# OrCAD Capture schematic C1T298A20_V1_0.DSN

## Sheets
1 000_Log: title: TELINK; rev: V1.3; note: C1T298A20
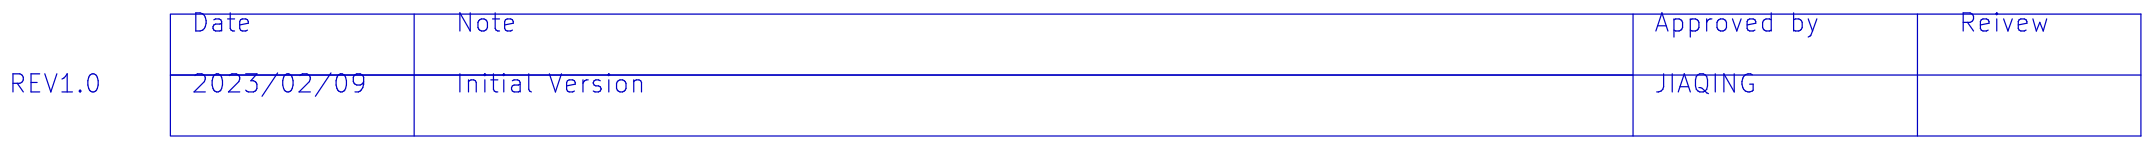
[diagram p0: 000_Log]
2 001_Structure
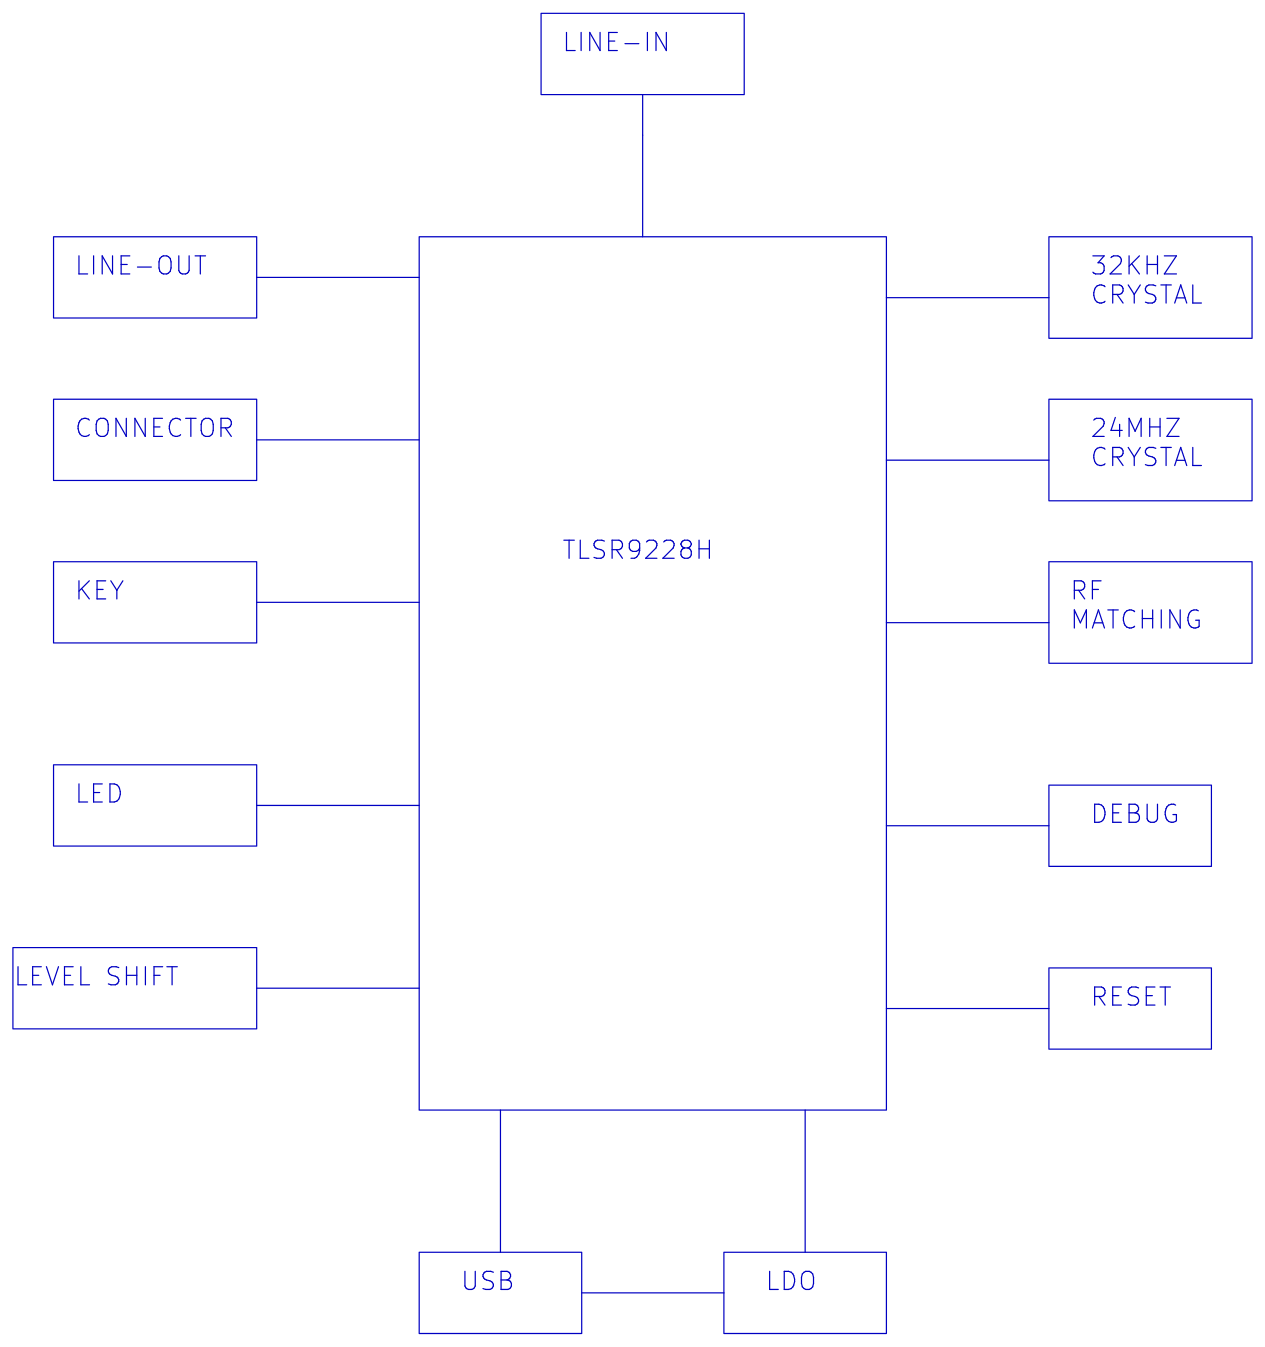
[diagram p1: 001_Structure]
3 002_MCU: size A3
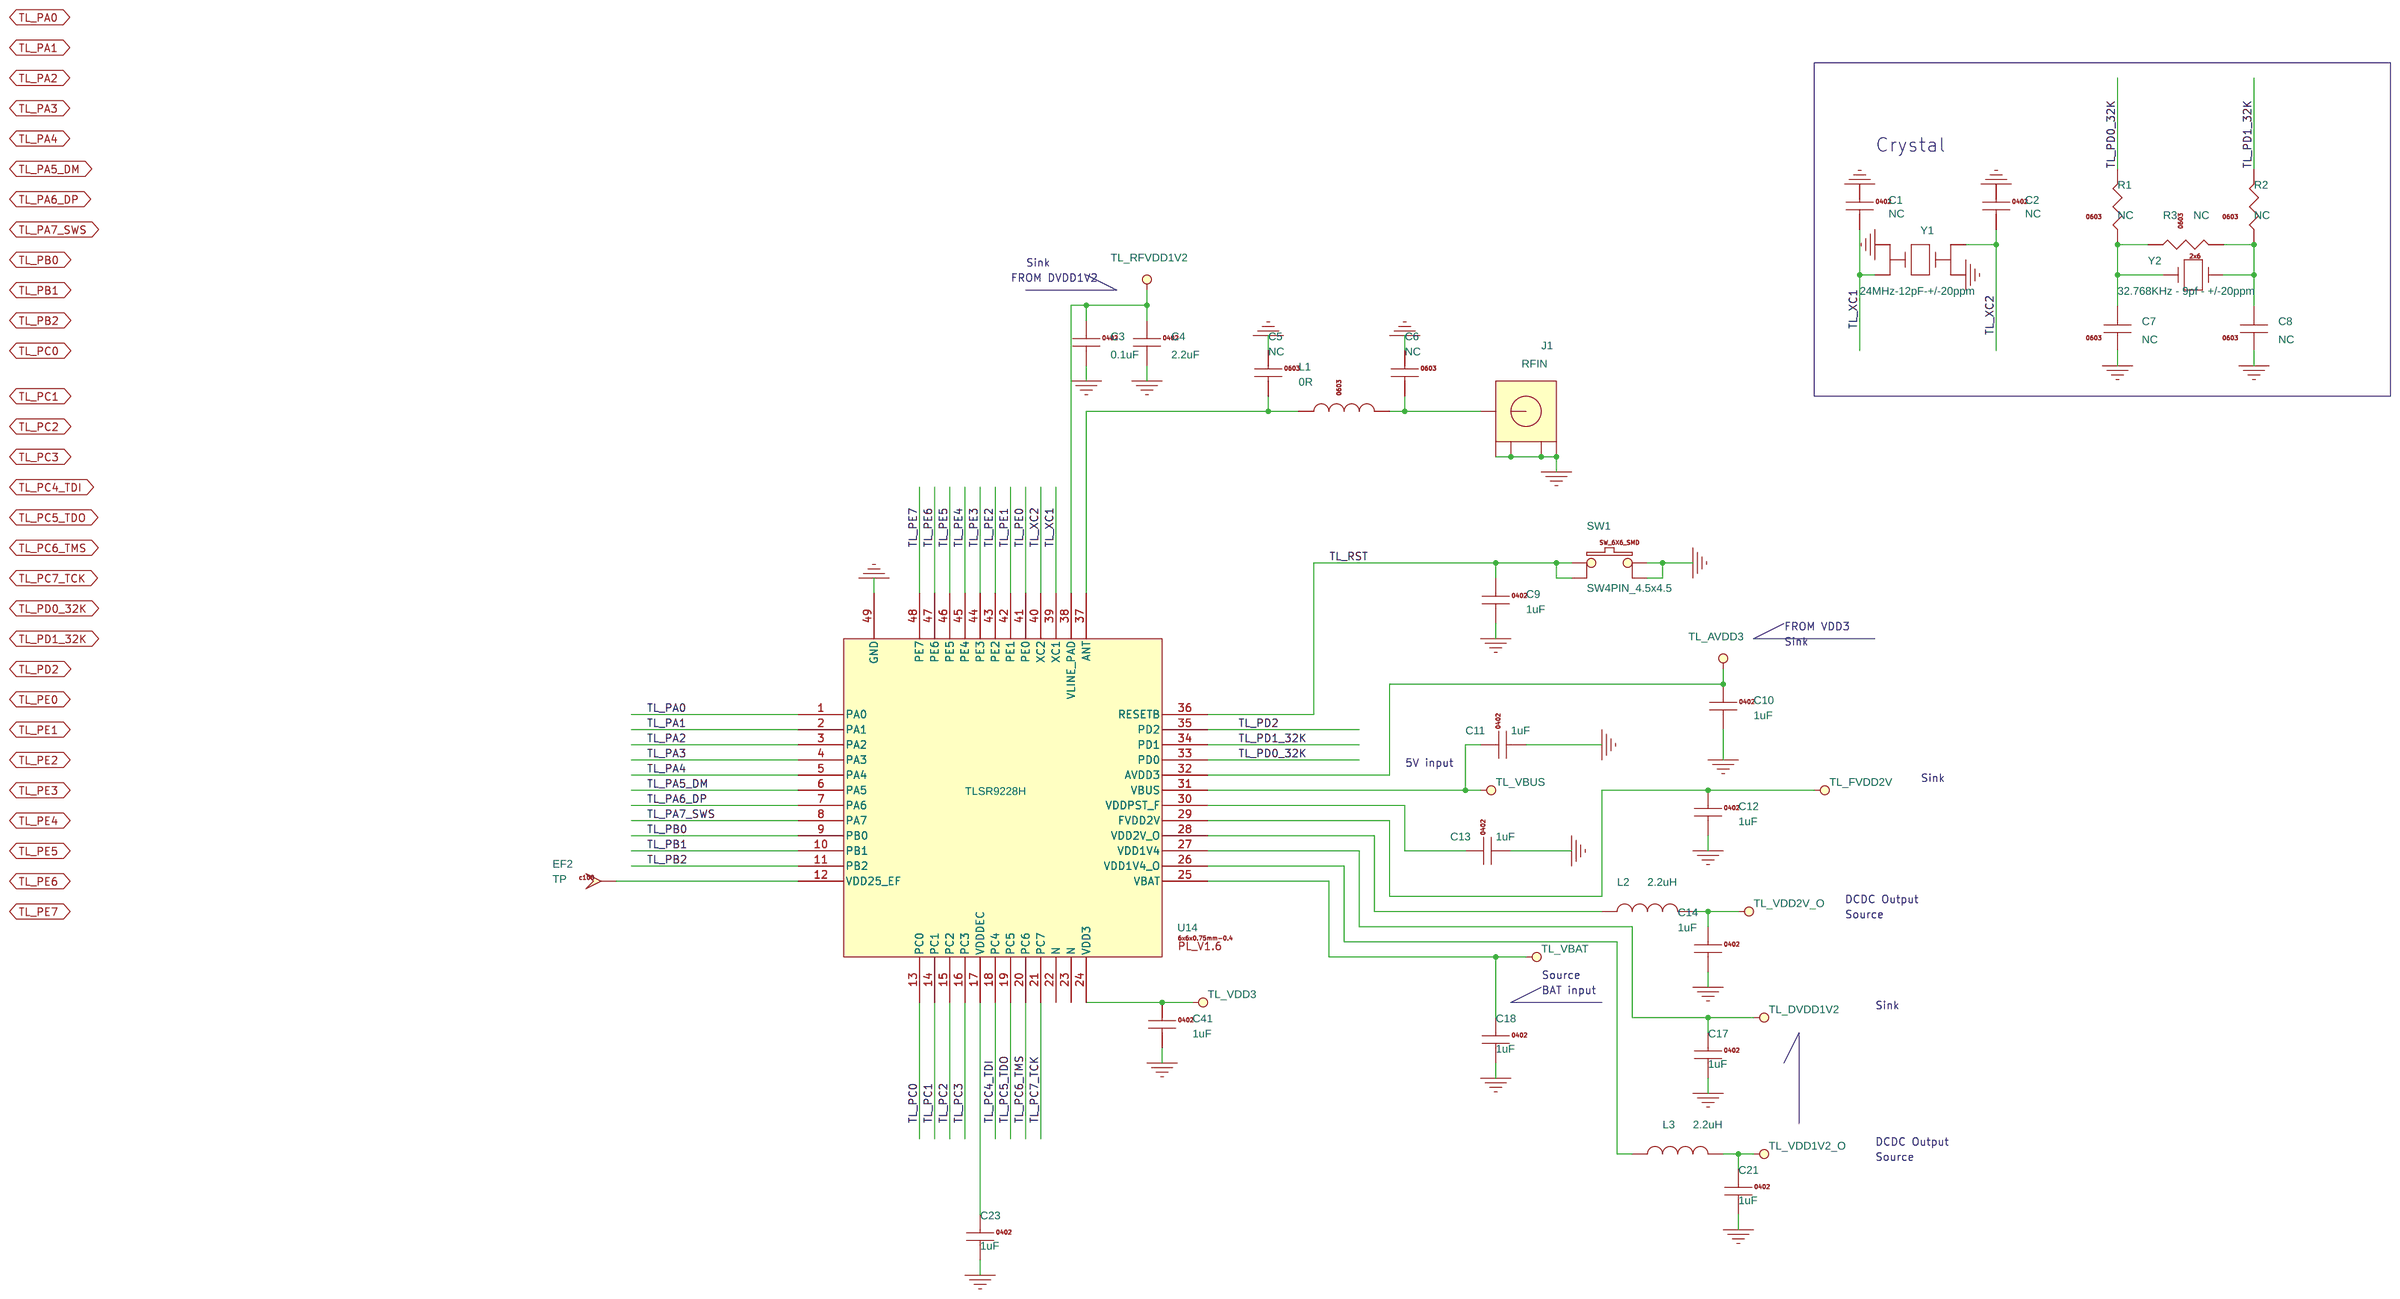
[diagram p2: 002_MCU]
4 003_INTERFACE: size A3
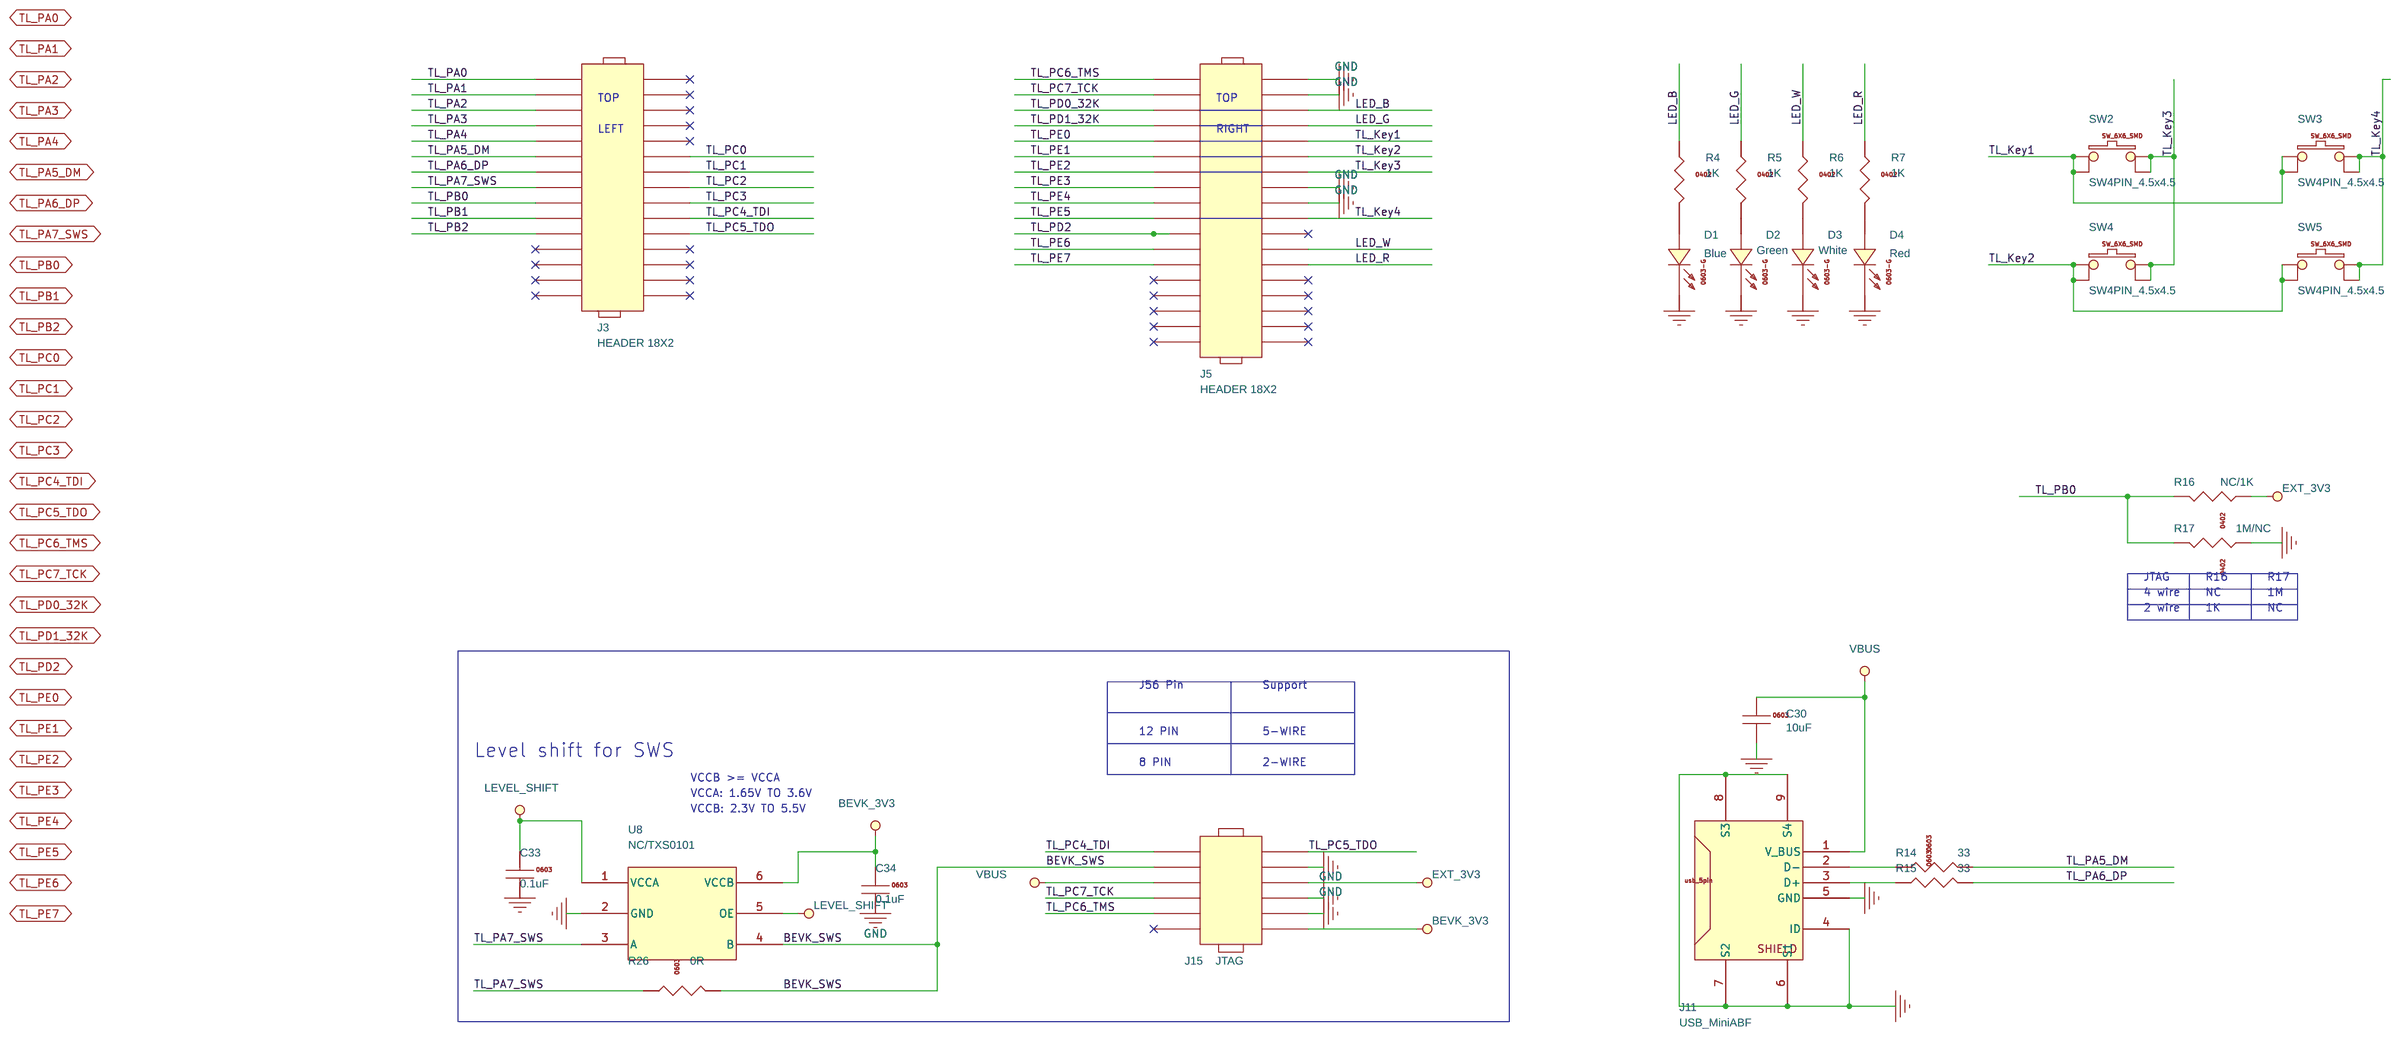
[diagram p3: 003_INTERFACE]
5 004_POWER: size A3
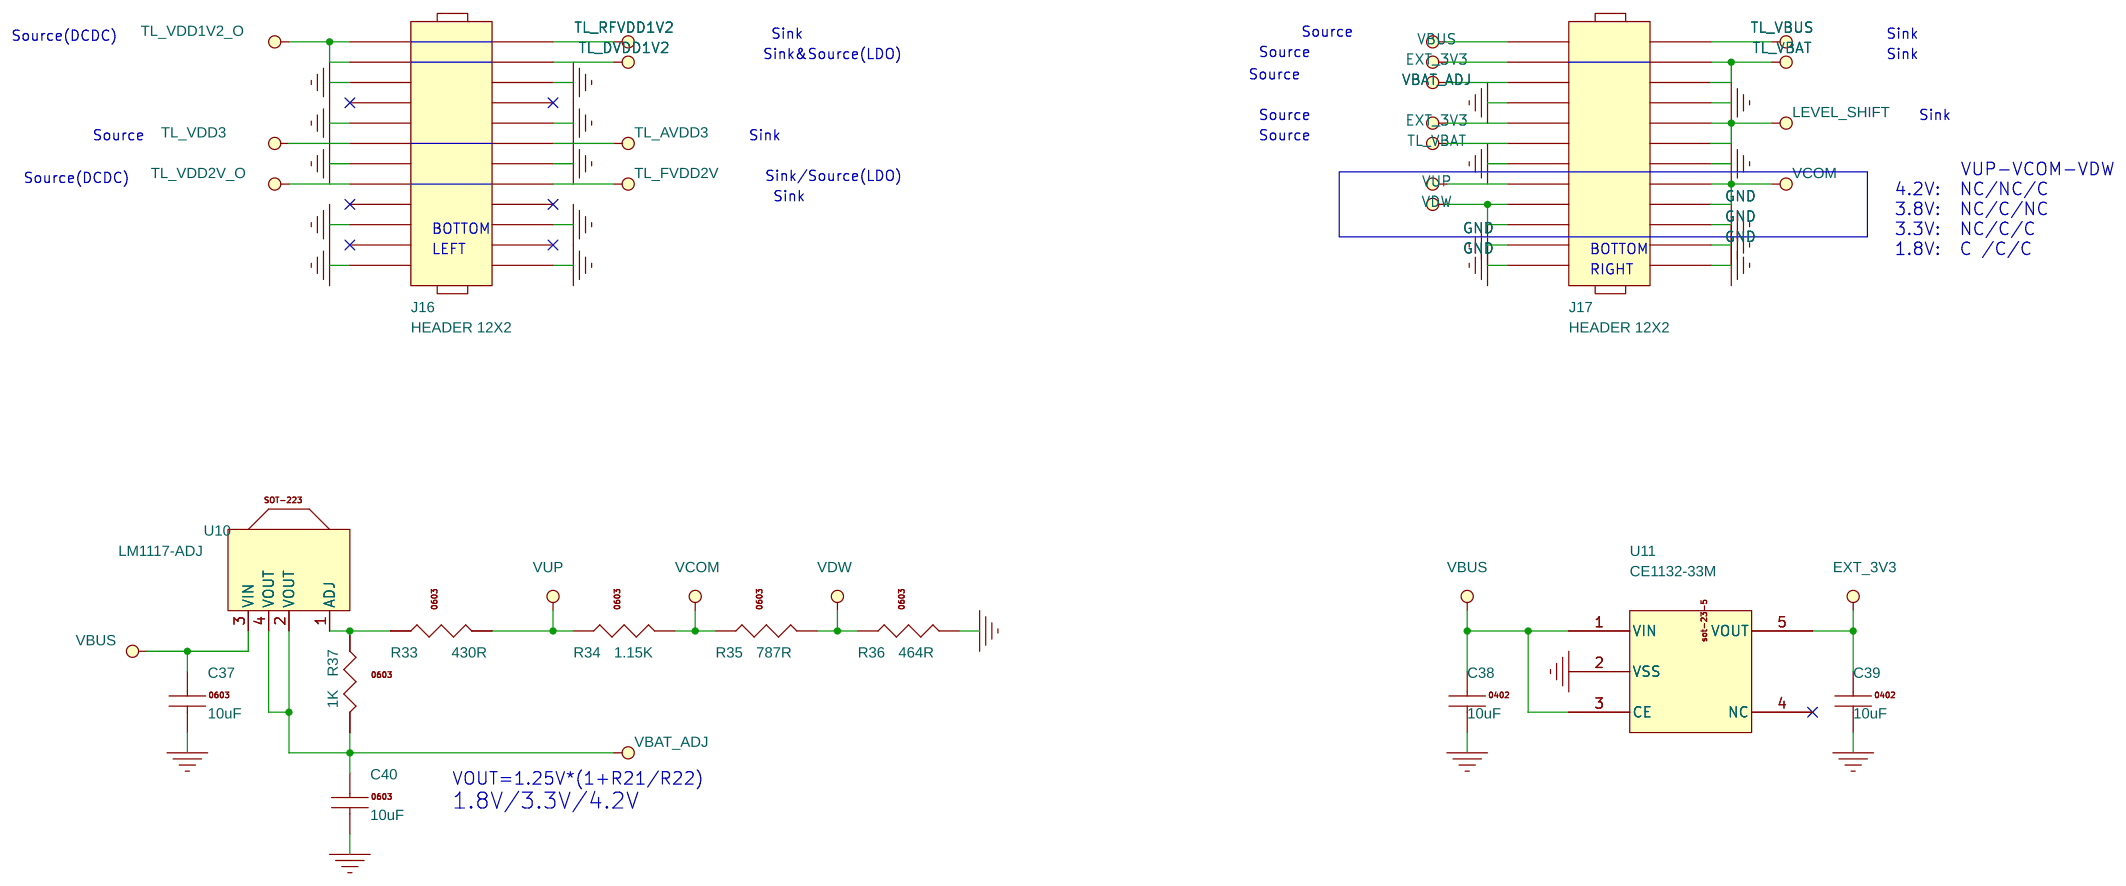
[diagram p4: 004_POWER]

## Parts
sheet 002_MCU
C1  NC  [0402]
C2  NC  [0402]
C3  0.1uF  [0402]
C4  2.2uF  [0402]
C5  NC  [0402]
C6  NC  [0402]
C7  NC  [0402]
C8  NC  [0402]
C9  1uF  [0402]
C10  1uF  [0402]
C11  1uF  [0402]
C12  1uF  [0402]
C13  1uF  [0402]
C14  1uF  [0402]
C17  1uF  [0402]
C18  1uF  [0402]
C21  1uF  [0402]
C23  1uF  [0402]
C41  1uF  [0402]
EF2  TP  [TP100]
J1  RFIN  [SMA-H]
L1  0R  [0402]
L2  2.2uH  [0805L]
L3  2.2uH  [0805L]
R1  NC  [0402]
R2  NC  [0402]
R3  NC  [0402]
SW1  SW4PIN_4.5x4.5  [SW_6X6_SMD]
U14  TLSR9228H  [qfn_6x6_48pin_0p4_4p2x4p2]
Y1  24MHz-12pF-+/-20ppm  [OSCCC250X320X110]
Y2  32.768KHz - 9pf - +/-20ppm  [OSC_2x6]
sheet 003_INTERFACE
C30  10uF  [0603C]
C33  0.1uF  [0402]
C34  0.1uF  [0402]
D1  Blue  [0603-LED]
D2  Green  [0603-LED]
D3  White  [0603-LED]
D4  Red  [0603-LED]
J3  HEADER 18X2  [smd254m-2x15_rx1_30y2_40]
J5  HEADER 18X2  [smd254m-2x18_rx1_30y2_40]
J11  USB_MiniABF  [USB-MINI-F5]
J15  JTAG  [hdr254f-2x6x850]
R4  1K  [0402]
R5  1K  [0402]
R6  1K  [0402]
R7  1K  [0402]
R14  33  [0402R]
R15  33  [0402R]
R16  NC/1K  [0402]
R17  1M/NC  [0402]
R26  0R  [0402R]
SW2  SW4PIN_4.5x4.5  [SW_6X6_SMD]
SW3  SW4PIN_4.5x4.5  [SW_6X6_SMD]
SW4  SW4PIN_4.5x4.5  [SW_6X6_SMD]
SW5  SW4PIN_4.5x4.5  [SW_6X6_SMD]
U8  NC/TXS0101  [sc70-6]
sheet 004_POWER
C37  10uF  [0603c]
C38  10uF  [0603C]
C39  10uF  [0603C]
C40  10uF  [0603C]
J16  HEADER 12X2  [smd254m-2x12_rx1_30y2_40]
J17  HEADER 12X2  [smd254m-2x12_rx1_30y2_40]
R33  430R  [0402]
R34  1.15K  [0402]
R35  787R  [0402]
R36  464R  [0402]
R37  1K  [0402]
U10  LM1117-ADJ  [sot-223]
U11  CE1132-33M  [sot-23-5]

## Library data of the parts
C1 C2 = C1005_NC
C3 C4 C9-C14 C17 C18 C21 C23 C38 C39 C41 = C1005X5R1C104K
C5-C8 = C1608_NC
EF2 = TestPad100
J1 = SMA_JACK_2: PART: RF
L1 = MLK1608_000R
L2 L3 = IND
R1-R3 R26 = RS0603K102JT
SW1-SW5 = SW_6X6_SMD_0
U14 = TLSR9228H_0
Y1 = CRYSTAL4_SM_0
Y2 = OSC_2x6_2pin_16Mhz
C30 C37 = C1608X5R0J106M
C33 C34 C40 = C1608X5R1C105M
D1-D4 = 0603D_Green
J3 = HEADER_18X2_0
J5 = HEADER_18X2
J11 = USB_MiniABF_5pin
J15 = HEADER_6X2
R4-R7 = RS0402K102JT
R14 R15 = RS0603K330JT
R16 R17 = RS0402K104JT
U8 = TXS0101
J16 J17 = HEADER_12X2
R33-R37 = RS0603K104JT
U10 = XC62FP3302_0.3V_SOT-89
U11 = XC6219_6.3V_SOT-23-5

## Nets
GND: C1.1 C2.1 C3.2 C4.2 C5.1 C6.1 C7.1 C8.1 C9.2 C10.2 C11.2 C12.2 C13.2 C14.2 C17.2 C18.2 C21.2 C23.2 C30.2 C33.2 C34.2 C37.2 C38.2 C39.2 C40.2 C41.2 D1.C(CATHODE) D2.C(CATHODE) D3.C(CATHODE) D4.C(CATHODE) J1.2 J1.3 J1.4 J1.5 J5.1 J5.3 J5.15 J5.17 J11.4(ID) J11.5(GND) J11.6(S1) J11.7(S2) J11.8(S3) J11.9(S4) J15.3 J15.5 J15.9 J16.5 J16.6 J16.9 J16.10 J16.13 J16.14 J16.19 J16.20 J16.23 J16.24 J17.7 J17.8 J17.13 J17.14 J17.19 J17.21 J17.22 J17.23 J17.24 R17.1 R36.2 SW1.3 SW1.4 U8.2(GND) U11.2(VSS) U14.49(GND) Y1.2 Y1.4
VBAT_ADJ: C40.1 J17.6 R37.2 U10.2(VOUT) U10.4(VOUT)
VBUS: C30.1 C37.1 C38.1 J11.1(V_BUS) J15.8 J17.2 U10.3(VIN) U11.1(VIN) U11.3(CE)
BEVK_3V3: C34.1 J15.1 U8.6(VCCB)
BEVK_SWS: J15.10 R26.2 U8.4(B)
EXT_3V3: C39.1 J15.7 J17.4 J17.10 R16.1 U11.5(VOUT)
LED_B: J5.5 R4.1
LED_G: J5.7 R5.1
LED_R: J5.25 R7.1
LED_W: J5.23 R6.1
LEVEL_SHIFT: C33.1 J17.9 J17.11 U8.1(VCCA) U8.5(OE)
N: U14.22(N) U14.23(N)
TL_AVDD3: C10.1 J16.11 U14.32(AVDD3)
TL_DVDD1V2: C17.1 J16.3 U14.27(VDD1V4)
TL_FVDD2V: C12.1 J16.15 U14.29(FVDD2V)
TL_Key1: J5.9 SW2.1 SW2.2 SW3.1 SW3.2
TL_Key2: J5.11 SW4.1 SW4.2 SW5.1 SW5.2
TL_Key3: J5.13 SW2.3 SW2.4 SW4.3 SW4.4
TL_Key4: J5.19 SW3.3 SW3.4 SW5.3 SW5.4
TL_PA0: U14.1(PA0)
TL_PA0 (page 003_INTERFACE): J3.2
TL_PA1: U14.2(PA1)
TL_PA1 (page 003_INTERFACE): J3.4
TL_PA2: U14.3(PA2)
TL_PA2 (page 003_INTERFACE): J3.6
TL_PA3: U14.4(PA3)
TL_PA3 (page 003_INTERFACE): J3.8
TL_PA4: U14.5(PA4)
TL_PA4 (page 003_INTERFACE): J3.10
TL_PA5_DM: U14.6(PA5)
TL_PA5_DM (page 003_INTERFACE): J3.12 R14.2
TL_PA6_DP: U14.7(PA6)
TL_PA6_DP (page 003_INTERFACE): J3.14 R15.2
TL_PA7_SWS: U14.8(PA7)
TL_PA7_SWS (page 003_INTERFACE): J3.16 R26.1 U8.3(A)
TL_PB0: U14.9(PB0)
TL_PB0 (page 003_INTERFACE): J3.18 R16.2 R17.2
TL_PB1: U14.10(PB1)
TL_PB1 (page 003_INTERFACE): J3.20
TL_PB2: U14.11(PB2)
TL_PB2 (page 003_INTERFACE): J3.22
TL_PC0: U14.13(PC0)
TL_PC0 (page 003_INTERFACE): J3.11
TL_PC1: U14.14(PC1)
TL_PC1 (page 003_INTERFACE): J3.13
TL_PC2: U14.15(PC2)
TL_PC2 (page 003_INTERFACE): J3.15
TL_PC3: U14.16(PC3)
TL_PC3 (page 003_INTERFACE): J3.17
TL_PC4_TDI: U14.18(PC4)
TL_PC4_TDI (page 003_INTERFACE): J3.19 J15.12
TL_PC5_TDO: U14.19(PC5)
TL_PC5_TDO (page 003_INTERFACE): J3.21 J15.11
TL_PC6_TMS: U14.20(PC6)
TL_PC6_TMS (page 003_INTERFACE): J5.2 J15.4
TL_PC7_TCK: U14.21(PC7)
TL_PC7_TCK (page 003_INTERFACE): J5.4 J15.6
TL_PD0_32K: R1.2 U14.33(PD0)
TL_PD0_32K (page 003_INTERFACE): J5.6
TL_PD1_32K: R2.2 U14.34(PD1)
TL_PD1_32K (page 003_INTERFACE): J5.8
TL_PD2: U14.35(PD2)
TL_PD2 (page 003_INTERFACE): J5.22
TL_PE0: U14.41(PE0)
TL_PE0 (page 003_INTERFACE): J5.10
TL_PE1: U14.42(PE1)
TL_PE1 (page 003_INTERFACE): J5.12
TL_PE2: U14.43(PE2)
TL_PE2 (page 003_INTERFACE): J5.14
TL_PE3: U14.44(PE3)
TL_PE3 (page 003_INTERFACE): J5.16
TL_PE4: U14.45(PE4)
TL_PE4 (page 003_INTERFACE): J5.18
TL_PE5: U14.46(PE5)
TL_PE5 (page 003_INTERFACE): J5.20
TL_PE6: U14.47(PE6)
TL_PE6 (page 003_INTERFACE): J5.24
TL_PE7: U14.48(PE7)
TL_PE7 (page 003_INTERFACE): J5.26
TL_RFVDD1V2: C3.1 C4.1 J16.1 U14.38(VLINE_PAD)
TL_RST: C9.1 SW1.1 SW1.2 U14.36(RESETB)
TL_VBAT: C18.1 J17.3 J17.5 J17.12 U14.25(VBAT)
TL_VBUS: C11.1 J17.1 U14.31(VBUS)
TL_VDD1V2_O: C21.1 J16.2 J16.4 L3.2
TL_VDD2V_O: C14.1 J16.16 L2.2
TL_VDD3: C41.1 J16.12 U14.24(VDD3)
TL_XC1: C1.2 U14.39(XC1) Y1.3
TL_XC2: C2.2 U14.40(XC2) Y1.1
VCOM: J17.15 J17.17 R34.2 R35.1
VDW: J17.18 J17.20 R35.2 R36.1
VUP: J17.16 R33.2 R34.1
N20012529: C7.2 R1.1 R3.1 Y2.1
N20012531: C8.2 R2.1 R3.2 Y2.2
N20028206: R33.1 R37.1 U10.1(ADJ)
N20031284: C23.1 U14.17(VDDDEC)
N20031302: L3.1 U14.26(VDD1V4_O)
N20031350: L2.1 U14.28(VDD2V_O)
N20031395: C13.1 U14.30(VDDPST_F)
N20031510: C6.2 J1.1 L1.2
N20031514: C5.2 L1.1 U14.37(ANT)
N20050417: J11.3(D+) R15.1
N20050429: J11.2(D-) R14.1
N20105309: EF2.1(TP) U14.12(VDD25_EF)
N20112719: D1.A(ANODE) R4.2
N20112722: D2.A(ANODE) R5.2
N20112727: D4.A(ANODE) R7.2
N20112736: D3.A(ANODE) R6.2

Not connected (* = marked no-connect by the designer): J3 1* 3* 5* 7* 9* 23* 24* 25* 26* 27* 28* 29* 30*; J5 21* 27* 28* 29* 30* 31* 32* 33* 34* 35* 36*; J15 2*; J16 7* 8* 17* 18* 21* 22*; U11 4(NC)*

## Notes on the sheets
sheet 1
- Date
- Note
- Approved by
- Reivew
- REV1.0
- 2023/02/09
- Initial Version
- JIAQING
sheet 2
- LINE-IN
- LINE-OUT
- 32KHZ
  CRYSTAL
- CONNECTOR
- 24MHZ
  CRYSTAL
- TLSR9228H
- KEY
- RF
  MATCHING
- LED
- DEBUG
- LEVEL SHIFT
- RESET
- USB
- LDO
sheet 3
- Crystal
- Sink
- FROM DVDD1V2
- FROM VDD3
- Sink
- 5V input
- Sink
- DCDC Output
- Source
- Source
- BAT input
- Sink
- DCDC Output
- Source
sheet 4
- TOP
- TOP
- LEFT
- RIGHT
- JTAG
- R16
- R17
- 4 wire
- NC
- 1M
- 2 wire
- 1K
- NC
- J56 Pin
- Support
- 12 PIN
- 5-WIRE
- Level shift for SWS
- VCCB >= VCCA
- 8 PIN
- 2-WIRE
- VCCA: 1.65V TO 3.6V
- VCCB: 2.3V TO 5.5V
sheet 5
- Source(DCDC)
- Sink
- Source
- Sink
- Sink&Source(LDO)
- Source
- Sink
- Source
- Source
- Sink
- Source
- Source
- Sink
- Source(DCDC)
- Sink/Source(LDO)
- VUP-VCOM-VDW
  4.2V:  NC/NC/C
  3.8V:  NC/C/NC
  3.3V:  NC/C/C
  1.8V:  C /C/C
- Sink
- BOTTOM
- LEFT
- BOTTOM
- RIGHT
- VOUT=1.25V*(1+R21/R22)
- 1.8V/3.3V/4.2V
